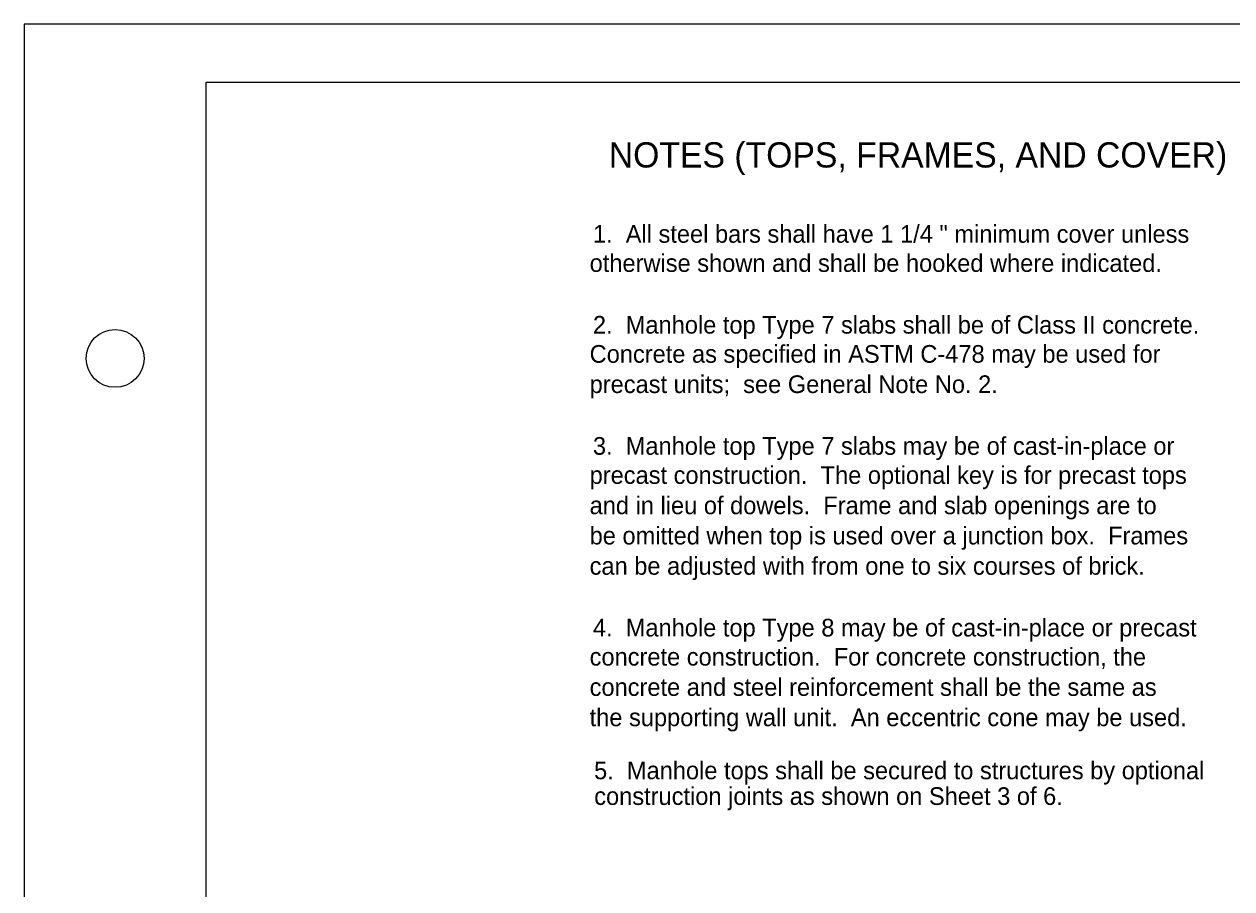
# Model space of a CAD drawing. Extents: x -7.1 to 10, y -5 to 6.
# Drawn here: x -7.065 to -2.543, y 2.73 to 5.966 of the extents above; entities that cross this region are included whole.
import ezdxf

# ---------------------------------------------------------------- set-up
doc = ezdxf.new("R2010")
doc.units = 0
doc.layers.add('Level 6', color=7, linetype='Continuous')
doc.layers.add('Level 60', color=7, linetype='Continuous')

msp = doc.modelspace()

# ---------------------------------------------------------------- linework, layer by layer
at = {"layer": 'Level 60'}
for points in [[(-7.0652, -5.0406), (9.9453, -5.0406), (9.9453, 5.9662), (-7.0652, 5.9662)], [(-6.384, 5.7493), (9.684, 5.7493), (9.684, -4.8063), (-6.384, -4.8063)]]:
    msp.add_lwpolyline(points, close=True, dxfattribs=at)
msp.add_circle((-6.7246, 4.7154), 0.1083, dxfattribs=at)

# ---------------------------------------------------------------- texts
at = {"layer": 'Level 6'}
msp.add_text('NOTES (TOPS, FRAMES, AND COVER)', height=0.094458, dxfattribs=at).set_placement((-4.8758, 5.4297))
for s, p in [('1.  All steel bars shall have 1 1/4 " minimum cover unless', (-4.9352, 5.1481)), ('    otherwise shown and shall be hooked where indicated.', (-5.0458, 5.039)), ('2.  Manhole top Type 7 slabs shall be of Class II concrete.', (-4.9352, 4.808)), ('    Concrete as specified in ASTM C-478 may be used for', (-5.0458, 4.699)), ('    precast units;  see General Note No. 2.', (-5.0458, 4.5856)), ('3.  Manhole top Type 7 slabs may be of cast-in-place or', (-4.9352, 4.3546)), ('    precast construction.  The optional key is for precast tops', (-5.0458, 4.2456)), ('    and in lieu of dowels.  Frame and slab openings are to', (-5.0458, 4.1322)), ('    be omitted when top is used over a junction box.  Frames', (-5.0458, 4.0189)), ('    can be adjusted with from one to six courses of brick.', (-5.0458, 3.9055)), ('4.  Manhole top Type 8 may be of cast-in-place or precast', (-4.9352, 3.6745)), ('    concrete construction.  For concrete construction, the', (-5.0458, 3.5655)), ('    concrete and steel reinforcement shall be the same as', (-5.0458, 3.4521)), ('    the supporting wall unit.  An eccentric cone may be used.', (-5.0458, 3.3388)), ('5.  Manhole tops shall be secured to structures by optional', (-4.9309, 3.1401)), ('    construction joints as shown on Sheet 3 of 6.', (-5.0286, 3.044))]:
    msp.add_text(s, height=0.066125, rotation=0, dxfattribs=at).set_placement(p)

doc.saveas('drawing.dxf')
